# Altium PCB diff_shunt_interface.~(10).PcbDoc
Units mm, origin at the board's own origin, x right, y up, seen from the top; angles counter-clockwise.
Board outline 10.67 x 15.24 mm, 2 copper layers (Top Layer, Bottom Layer), stack 0.409 mm thick; 5 components, 6 nets, 12 pads, 108 vias.
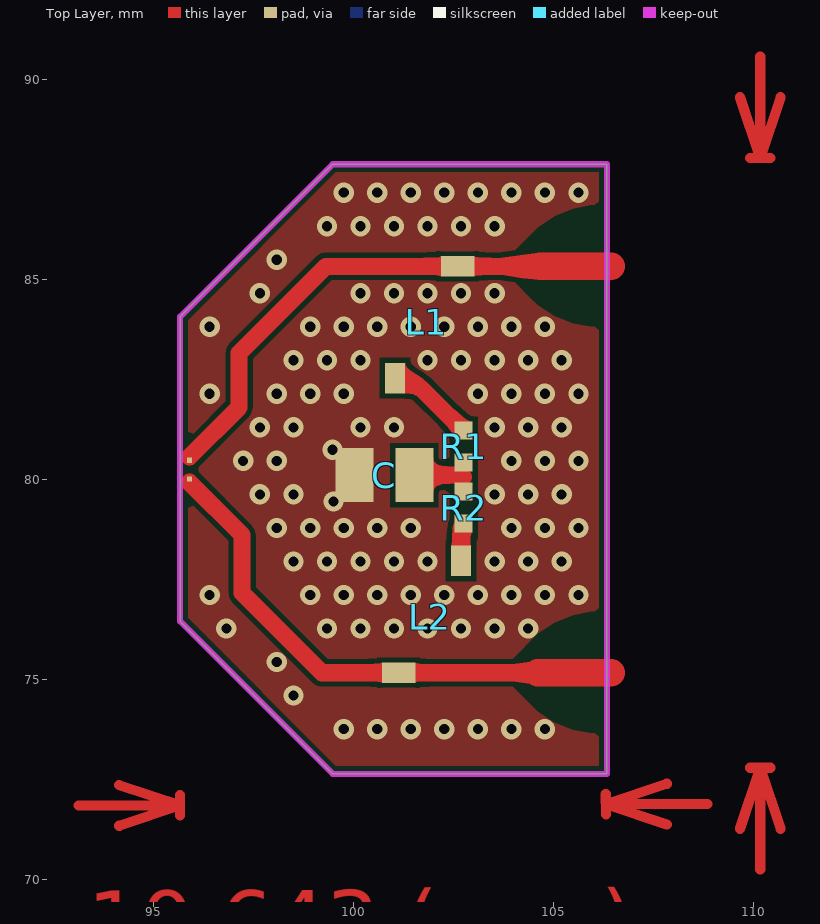
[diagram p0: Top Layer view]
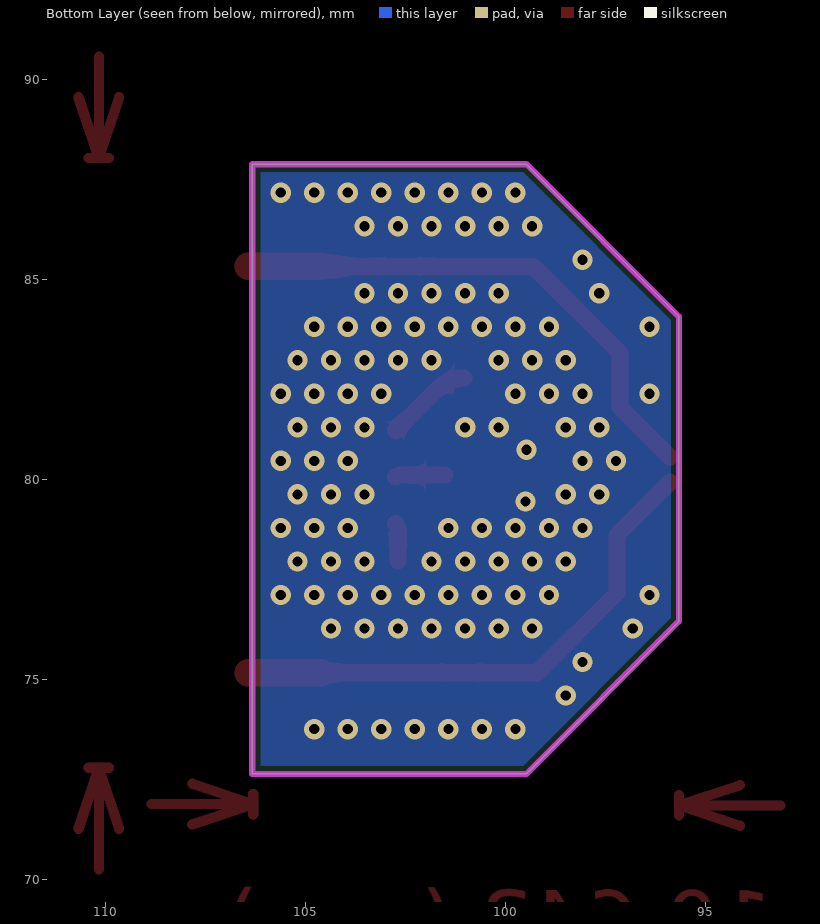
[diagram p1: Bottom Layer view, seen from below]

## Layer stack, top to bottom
Top Solder: solder mask 0.0102, Solder Resist, Dk 3.5
Top Layer: signal copper 0.0356
Dielectric 1: dielectric 0.3378, FR-4, Dk 3.66
Bottom Layer: signal copper 0.0356
Bottom Solder: solder mask 0.0102, Solder Resist, Dk 3.5

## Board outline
95.656,76.454 99.466,72.644 106.324,72.644 106.324,87.884 99.466,87.884 95.656,84.074

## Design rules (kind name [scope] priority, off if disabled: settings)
Clearance Clearance_3 [InNet('NetL2_2') vs OnLayer('Keep-Out Layer')] p1: gap=-2.54 ignorepadtopadclearanceinfootprint=FALSE except(0: Arc-Hole Track-Hole SMDPad-Hole THPad-Hole Via-Hole Fill-Hole Poly-Hole Region-Hole Text-Hole)
Clearance Clearance_2 [InNet('NetL1_2') vs OnLayer('Keep-Out Layer')] p2: gap=-2.54 ignorepadtopadclearanceinfootprint=FALSE except(0: Arc-Hole Track-Hole SMDPad-Hole THPad-Hole Via-Hole Fill-Hole Poly-Hole Region-Hole Text-Hole)
Clearance Clearance_1 [InNet('No Net') vs InNet('GND')] p3: gap=1.27 ignorepadtopadclearanceinfootprint=FALSE except(0: Arc-Hole Track-Hole SMDPad-Hole THPad-Hole Via-Hole Fill-Hole Poly-Hole Region-Hole Text-Hole)
Clearance [All] p4: gap=0.127 ignorepadtopadclearanceinfootprint=FALSE except(0: Arc-Hole Track-Hole SMDPad-Hole THPad-Hole Via-Hole Fill-Hole Poly-Hole Region-Hole Text-Hole)
PolygonConnect [All] p1: connectstyle=Direct reliefconductorwidth=0.254 reliefentries=4 polygonreliefangle="90 Angle" airgapwidth=0.254
RoutingVias [All] p1: holewidth=0.711 width=1.27 viastyle="Through Hole" minholewidth=0.711 minwidth=1.27 maxholewidth=0.711 maxwidth=1.27
SolderMaskExpansion [All] p1: expansion=0.102 istentingtop=FALSE
Width [All] p1: maxlimit=1.27 minlimit=0.203 preferedwidth=0.427 impedanceprofiledriven=TRUE impedanceprofileid={C9EE0A32-63B8-435B-8C3B-82C28B80C81C} impedanceprofilevalue=50.000000 minimp=50.000000 maximp=50.000000 favimp=50.000000
30 further rules are at their usual default settings.

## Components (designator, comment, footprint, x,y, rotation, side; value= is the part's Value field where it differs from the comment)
C "CBR08C470FAGAC" FP-CBR08C-MFG 100.762,80.112 r0 top value="47 pF"
L1 "506WLSM0R70KT619T" 506WLS 101.727,83.998 r180 top
L2 "506WLSM0R70KT619T" 506WLS 101.981,76.505 r0 top
R1 "50R 0402" RESC1005X35X20LL05T10 102.743,80.823 r90 top
R2 "50R 0402" RESC1005X35X20LL05T10 102.743,79.299 r90 top

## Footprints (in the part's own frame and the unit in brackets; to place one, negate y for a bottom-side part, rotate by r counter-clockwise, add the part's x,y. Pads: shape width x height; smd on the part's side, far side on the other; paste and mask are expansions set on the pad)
506WLS [mil] "ATC conical inductor"
  rect 20x30 smd mask+1.97: 1(27.5,57.5)
  rect 33x20 smd mask+1.97: 2(-34,-52.5)
  body extent -45,-58 35,69, height 105
FP-CBR08C-MFG [mm]
  rect 0.95x1.35 smd paste+0 mask+0: 1(-0.75,0) 2(0.75,0)
  body extent -1.4,-0.85 1.4,0.85, height 0.25
RESC1005X35X20LL05T10 [mm] "Chip Resistor, 2-Leads, Body 1.00x0.50mm, IPC High Density"
  rect 0.45x0.45 smd: 1(-0.4,0) 2(0.4,0)
  body extent -0.53,-0.27 0.53,0.28, height 0.35

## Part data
C: library part CMP-03020-025427-1, "CAP CER 47PF 250V C0G/NP0 0805", Capacitance="47 pF", Manufacturer=KEMET, Package=CBR08C, Temperature="-55°C to +125°C", Temperature Characteristic=C0G, Temperature Coefficient=30ppm/°C, Temperature Range High=+125°C, Temperature Range Low=-55°C, Tolerance=0.01, Voltage Rating="250 V"
L1 L2: "coilcraft 700nH"
R1 R2: library part CMP-2002-03144-1, Manufacturer="TE Connectivity / AMP", Part Number=CPF0402B15K8E1

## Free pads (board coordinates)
  rect 0.13x0.13 smd: 2(95.886,80.014) 3(95.886,80.484)

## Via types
v1: diameter 0.508, hole 0.254, Top Layer to Bottom Layer, 108 vias

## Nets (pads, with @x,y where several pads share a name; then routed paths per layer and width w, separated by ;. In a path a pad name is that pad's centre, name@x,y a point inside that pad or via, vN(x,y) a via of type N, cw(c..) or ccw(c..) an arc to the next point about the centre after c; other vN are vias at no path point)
GND: C.1
  other v1: 99.746,73.762 100.584,73.762 101.422,73.762 102.26,73.762 103.099,73.762 103.937,73.762 104.775,73.762 98.489,74.6 98.069,75.438 96.812,76.276 99.327,76.276 100.165,76.276 101.003,76.276 101.841,76.276 102.679,76.276 103.518,76.276 104.356,76.276 96.393,77.114 98.908,77.114 99.746,77.114 100.584,77.114 101.422,77.114 102.26,77.114 103.099,77.114 103.937,77.114 104.775,77.114 105.613,77.114 98.489,77.953 99.327,77.953 100.165,77.953 101.003,77.953 101.841,77.953 103.518,77.953 104.356,77.953 105.194,77.953 98.069,78.791 98.908,78.791 99.746,78.791 100.584,78.791 101.422,78.791 103.937,78.791 104.775,78.791 105.613,78.791 99.492,79.451 97.65,79.629 98.489,79.629 103.518,79.629 104.356,79.629 105.194,79.629 97.231,80.467 98.069,80.467 103.937,80.467 104.775,80.467 105.613,80.467 99.466,80.747 97.65,81.305 98.489,81.305 100.165,81.305 101.003,81.305 103.518,81.305 104.356,81.305 105.194,81.305 96.393,82.144 98.069,82.144 98.908,82.144 99.746,82.144 103.099,82.144 103.937,82.144 104.775,82.144 105.613,82.144 98.489,82.982 99.327,82.982 100.165,82.982 101.841,82.982 102.679,82.982 103.518,82.982 104.356,82.982 105.194,82.982 96.393,83.82 98.908,83.82 99.746,83.82 100.584,83.82 101.422,83.82 102.26,83.82 103.099,83.82 103.937,83.82 104.775,83.82 97.65,84.658 100.165,84.658 101.003,84.658 101.841,84.658 102.679,84.658 103.518,84.658 98.069,85.496 99.327,86.335 100.165,86.335 101.003,86.335 101.841,86.335 102.679,86.335 103.518,86.335 99.746,87.173 100.584,87.173 101.422,87.173 102.26,87.173 103.099,87.173 103.937,87.173 104.775,87.173 105.613,87.173
NetC_2: C.2 R1.1 R2.2 | length 1.2
  Top Layer w0.427: C.2 102.62,80.112 cw(c102.62,79.938) 102.743,80.061
NetL1_1: L1.1 R1.2 | length 2.2
  Top Layer w0.427: L1.1 cw(c101.028,81.572) 101.711,82.254 R1.2
NetL1_2: L1.2 pad.3 | length 13.3
  Top Layer w0.427: 95.886,80.564 97.131,81.809 97.131,83.161 99.301,85.331 L1.2 104.661,85.331
  Top Layer w0.693: 104.661,85.331 106.426,85.331
NetL2_1: L2.1 R2.1 | length 1
  Top Layer w0.427: L2.1 102.679,78.745 cw(c102.896,78.745) R2.1
NetL2_2: L2.2 pad.2 | length 13.4
  Top Layer w0.427: 95.886,79.934 97.206,78.614 97.206,77.165 99.2,75.171 L2.2 104.597,75.171
  Top Layer w0.693: 104.597,75.171 106.426,75.171
copper on no net: | length 25
  Top Layer w0.254: 93.115,71.851 95.655,71.857 ; 94.13,72.361 95.655,71.857 ; 94.133,71.345 95.655,71.857 ; 95.655,72.111 95.656,71.603 ; 106.298,72.136 106.299,71.628 ; 107.821,72.394 106.298,71.882 ; 107.824,71.378 106.298,71.882 ; 108.838,71.888 106.298,71.882 ; 109.652,71.272 110.16,72.796 ; 109.652,89.56 110.16,88.036 ; 109.906,72.796 110.414,72.796 ; 109.906,88.036 110.414,88.036 ; 110.16,70.256 110.16,72.796 ; 110.16,90.576 110.16,88.036 ; 110.668,71.272 110.16,72.796 ; 110.668,89.56 110.16,88.036

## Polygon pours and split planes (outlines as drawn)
GND on Bottom Layer "Bottom Layer-No Net" (solid, pour order 0): 95.656,84.074 99.466,87.884 106.324,87.884 106.324,72.644 99.466,72.644 95.656,76.454
no net on Top Solder "NONET_L01_P002" (solid, pour order 2): 95.656,76.454 99.466,72.644 106.324,72.644 106.324,87.884 99.466,87.884 95.656,84.074
no net on Bottom Solder (solid, pour order 3): 95.656,76.454 99.466,72.644 106.324,72.644 106.324,87.884 99.466,87.884 95.656,84.074
GND on Top Layer "GND_L01_P001" (solid, pour order 1): 95.631,76.454 99.441,72.644 106.299,72.644 106.299,87.884 99.441,87.884 95.631,84.074

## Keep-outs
Keep-Out Layer:
  the board outline again, w0.152

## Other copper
Top Layer:
  pour cut-out: 103.619,85.331 104.412,86.124 cw(c106.208,84.328) 106.208,86.868 106.426,86.868 106.426,83.82 106.183,83.82 cw(c106.165,86.317) 104.412,84.539
  pour cut-out: 103.619,75.171 104.412,75.964 cw(c106.208,74.168) 106.208,76.708 106.426,76.708 106.426,73.66 106.183,73.66 cw(c106.165,76.157) 104.412,74.379
  text "15.24 (mm)" at 113.816,73.535 h1.52 r90
  text "10.643 (mm)" at 93.343,68.194 h1.52 r0.14

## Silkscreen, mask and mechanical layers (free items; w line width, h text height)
Top Solder:
  lines w0.693: 104.648,75.184 106.299,75.184 ; 104.661,85.344 106.312,85.344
